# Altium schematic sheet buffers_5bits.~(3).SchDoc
size A4
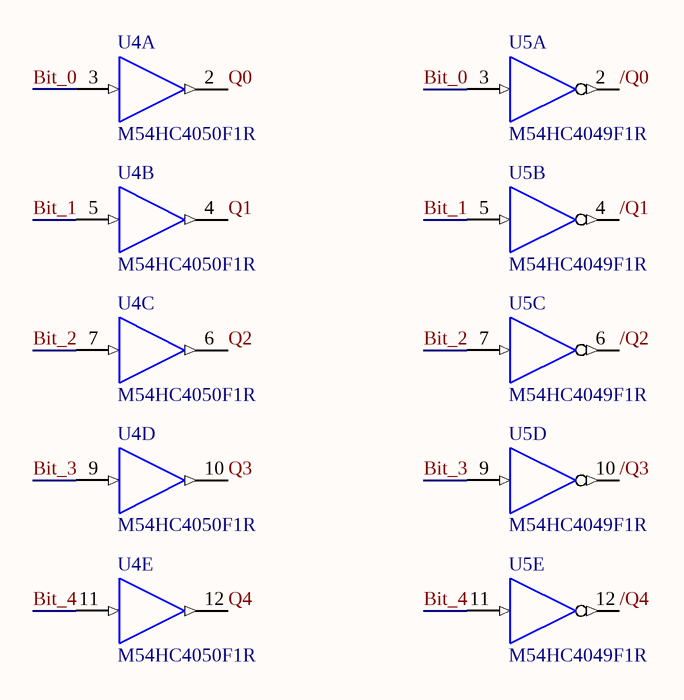
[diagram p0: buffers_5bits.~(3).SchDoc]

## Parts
U4  M54HC4050F1R  [DIP16]  (parts A,B,C,D,E of 6)
U5  M54HC4049F1R  [DIP16]  (parts A,B,C,D,E of 6)

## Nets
GND: U4.8(GND) U5.8(GND)
VCC: U4.1(VCC) U5.1(VCC)
/Q0: U5.2(Y)
/Q1: U5.4(Y)
/Q2: U5.6(Y)
/Q3: U5.10(Y)
/Q4: U5.12(Y)
Bit_0: U4.3(A) U5.3(A)
Bit_1: U4.5(A) U5.5(A)
Bit_2: U4.7(A) U5.7(A)
Bit_3: U4.9(A) U5.9(A)
Bit_4: U4.11(A) U5.11(A)
Q0: U4.2(Y)
Q1: U4.4(Y)
Q2: U4.6(Y)
Q3: U4.10(Y)
Q4: U4.12(Y)

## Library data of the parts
U4 = M54HC4050F1R: Hex Buffer/Converter Non-Inverting; Note: Pins 13 and 16 are not connected and not drawn.
U5 = M54HC4049F1R: Hex Buffer/Converter Invertering; Note: Pins 13 and 16 are not connected and not drawn.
